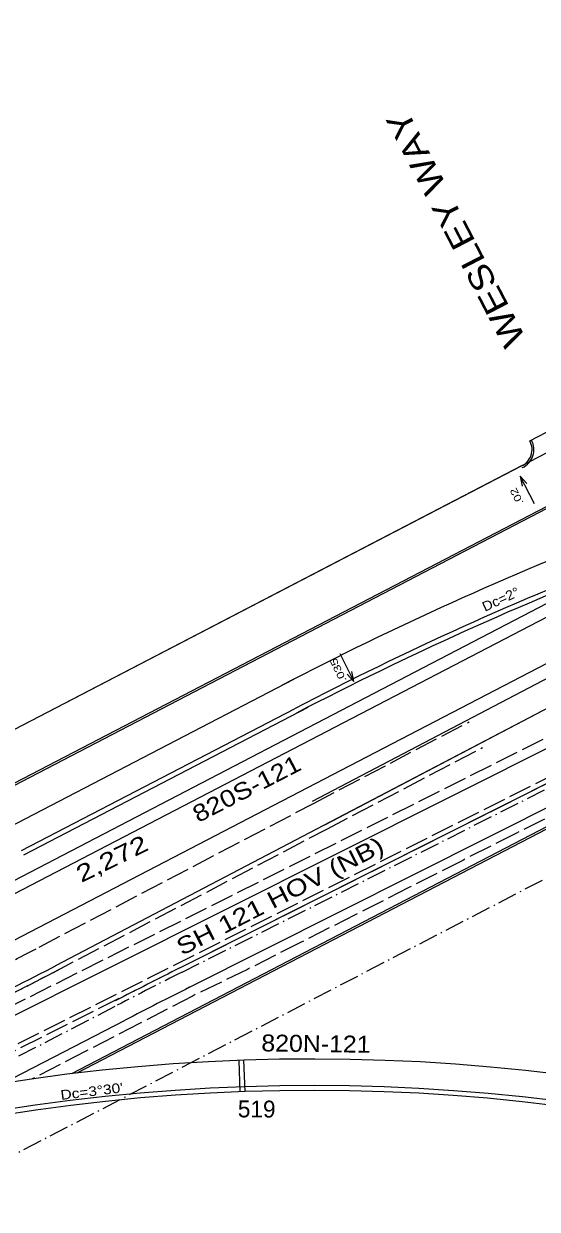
# Model space of a CAD drawing. Extents: x 2354993 to 2372084, y 6966390 to 6990057.
# Drawn here: x 2363006 to 2363431, y 6978118 to 6979100 of the extents above; entities that cross this region are included whole.
import ezdxf
from ezdxf.enums import TextEntityAlignment as Align

# ---------------------------------------------------------------- set-up
doc = ezdxf.new("R2010")
doc.units = 0
doc.header["$LTSCALE"] = 3.2
doc.linetypes.add('DOT_DASHED', pattern=[7.7, 5, -1.2, 0.3, -1.2])
doc.linetypes.add('LONG_DASHED', pattern=[7.5, 6, -1.5])
for name, color, linetype, lineweight in [('13', 7, 'Continuous', 13), ('17', 7, 'Continuous', 13), ('19', 7, 'Continuous', 13), ('25', 7, 'Continuous', 13), ('4', 7, 'Continuous', 13), ('5', 7, 'Continuous', 13), ('6', 7, 'Continuous', 13), ('9', 7, 'Continuous', 13)]:
    doc.layers.add(name, color=color, linetype=linetype, lineweight=lineweight)

msp = doc.modelspace()

# ---------------------------------------------------------------- linework, layer by layer
at = {"layer": '17'}
for p, q in [((2363268.695, 6978481.439), (2363677.359, 6978693.821)), ((2363183.998, 6978240.992), (2363184.891, 6978215.034)), ((2363187.996, 6978241.129), (2363188.889, 6978215.172))]:
    msp.add_line(p, q, dxfattribs=at)
at = {"layer": '19'}
for p, q in [((2363417.054, 6978724.995), (2363418.784, 6978716.872)), ((2363417.054, 6978724.995), (2363422.81, 6978719)), ((2363429.128, 6978702.214), (2363417.054, 6978724.995)), ((2363267.755, 6978578.025), (2363279.347, 6978554.995)), ((2363279.347, 6978554.995), (2363273.719, 6978561.11)), ((2363279.347, 6978554.995), (2363277.788, 6978563.153))]:
    msp.add_line(p, q, dxfattribs=at)
at = {"layer": '25'}
for p, q in [((2363038.234, 6978322.559), (2364007.4, 6978830.292)), ((2358006.591, 6975920.846), (2363488.891, 6978770.331)), ((2362811.106, 6978184.667), (2363604.71, 6978582.7)), ((2363003.914, 6978414.83), (2363230.047, 6978532.352)), ((2363143.211, 6978301.576), (2363589.111, 6978525.607)), ((2362988.207, 6978222.005), (2363089.737, 6978274.358))]:
    msp.add_line(p, q, dxfattribs=at)
at = {"layer": '25', "linetype": 'LONG_DASHED'}
for p, q in [((2362775.435, 6978175.726), (2363601.123, 6978589.851)), ((2363618.55, 6978565.019), (2362905.562, 6978206.794)), ((2363135.13, 6978317.66), (2363581.03, 6978541.691)), ((2363245.903, 6978453.932), (2363374.908, 6978521.516)), ((2363257.039, 6978432.672), (2363386.045, 6978500.257)), ((2363018.694, 6978334.9), (2363245.903, 6978453.932)), ((2363458.934, 6978451.609), (2363414.156, 6978429.36)), ((2363029.83, 6978313.64), (2363257.039, 6978432.672)), ((2363414.13, 6978429.346), (2363369.523, 6978406.758)), ((2363369.523, 6978406.757), (2363324.916, 6978384.169)), ((2363324.916, 6978384.168), (2363280.309, 6978361.58)), ((2363280.309, 6978361.579), (2363235.702, 6978338.991)), ((2363235.702, 6978338.99), (2363191.095, 6978316.402)), ((2363191.154, 6978316.43), (2363146.169, 6978294.605)), ((2363084.717, 6978292.33), (2362920.65, 6978209.898)), ((2363146.082, 6978294.561), (2363101.663, 6978271.606)), ((2363101.663, 6978271.606), (2363057.244, 6978248.651)), ((2363057.244, 6978248.651), (2363012.825, 6978225.696))]:
    msp.add_line(p, q, dxfattribs=at)
at = {"layer": '25'}
for centre, radius, start, end in [((2364544.669, 6976002.774), 2850.789, 111.22127, 117.46089), ((2365709.196, 6973194.37), 5715.578, 116.67607, 117.27757)]:
    msp.add_arc(centre, radius, start, end, dxfattribs=at)
at = {"layer": '25', "linetype": 'LONG_DASHED'}
for centre, radius, start, end in [((2361957.93, 6980359.697), 2285.831, 293.48147, 297.64944), ((2361957.927, 6980359.696), 2309.831, 293.48137, 297.6495), ((2365709.196, 6973194.37), 5733.578, 116.67607, 117.27757)]:
    msp.add_arc(centre, radius, start, end, dxfattribs=at)
at = {"layer": '4'}
msp.add_line((2362757.154, 6978215.587), (2363268.695, 6978481.438), dxfattribs=at)
at = {"layer": '5'}
for p, q in [((2363255.18, 6978436.214), (2364007.4, 6978830.292)), ((2363244.971, 6978455.701), (2363891.715, 6978794.521)), ((2363425.177, 6978754.243), (2363463.775, 6978774.478)), ((2362087.371, 6978041.876), (2363419.143, 6978734.078)), ((2362654.988, 6978292.473), (2363507.292, 6978735.395)), ((2362655.626, 6978291.114), (2363508.018, 6978734.082)), ((2362391.142, 6978063.692), (2363583.984, 6978683.611)), ((2363248.405, 6978520.48), (2363498.513, 6978650.46)), ((2362993.757, 6978434.346), (2363229.499, 6978556.861)), ((2363135.13, 6978317.66), (2363581.03, 6978541.691)), ((2363005.748, 6978411.277), (2363241.489, 6978533.791)), ((2363620.009, 6978528.496), (2363045.424, 6978230.005)), ((2362329.78, 6978043.07), (2363248.405, 6978520.479)), ((2363620.695, 6978527.162), (2363049.66, 6978230.516))]:
    msp.add_line(p, q, dxfattribs=at)
for centre, radius, start, end in [((2363412.177, 6978747.044), 14.86, 294.19474, 28.97554), ((2363412.177, 6978747.044), 16.36, 294.19474, 28.97554), ((2364544.669, 6976002.774), 2872.789, 111.22127, 117.46089), ((2364544.669, 6976002.774), 2846.789, 111.22127, 117.46089), ((2361968.189, 6980365.073), 2305.831, 293.48164, 297.64942), ((2361968.189, 6980365.073), 2309.831, 293.48164, 297.64942), ((2365709.196, 6973194.37), 5733.578, 116.67607, 117.27757), ((2363244.672, 6976597.082), 1645.014, 38.12295, 103.3303), ((2363244.672, 6976597.082), 1623.014, 38.12295, 103.3303), ((2363244.672, 6976597.082), 1619.014, 38.12295, 103.3303)]:
    msp.add_arc(centre, radius, start, end, dxfattribs=at)
at = {"layer": '6', "linetype": 'DOT_DASHED'}
for p, q in [((2363136.926, 6978314.086), (2363582.826, 6978538.117)), ((2360272.717, 6976747.357), (2363548.144, 6978448.903)), ((2360272.718, 6976747.358), (2363548.137, 6978448.9)), ((2360272.718, 6976747.358), (2363548.137, 6978448.9)), ((2362716.922, 6978097.869), (2363083.321, 6978286.801))]:
    msp.add_line(p, q, dxfattribs=at)
msp.add_arc((2365709.196, 6973194.37), 5729.578, 116.67607, 117.27757, dxfattribs=at)
at = {"layer": '9'}
msp.add_arc((2360722.521, 6984327.136), 5729.573, 359.50797, 359.50797, dxfattribs=at)

# ---------------------------------------------------------------- texts
at = {"layer": '13', "width": 1.2}
msp.add_text('WESLEY WAY', height=20, rotation=117.447, dxfattribs=at).set_placement((2363372.707, 6978934.43), align=Align.CENTER)
at = {"layer": '13'}
for s, rotation, width, p in [('820S-121', 27.223, 1.2, (2363150.343, 6978437.629)), ('2,272', 26.014, 1.35, (2363053.466, 6978387.998)), ('SH 121 HOV (NB)', 27.223, 1.25, (2363136.887, 6978327.523)), ('820N-121', 359.235, 1.1, (2363202.628, 6978248.531))]:
    msp.add_text(s, height=14, rotation=rotation, dxfattribs=dict(at, width=width)).set_placement(p)
msp.add_text('519', height=14, rotation=359.616, dxfattribs=at).set_placement((2363183.176, 6978193.859))
at = {"layer": '17'}
for s, height, rotation, width, p in [('Dc=2°', 7.999, 24.802, 1.1, (2363387.985, 6978612.641)), ("Dc=3°30'", 8, 7.036, 1.2, (2363036.778, 6978208.259))]:
    msp.add_text(s, height=height, rotation=rotation, dxfattribs=dict(at, width=width)).set_placement(p)
at = {"layer": '19'}
for s, height, rotation, width, p in [('.02', 6, 117.046, 1.3, (2363420.257, 6978703.128)), ('.035', 5.999, 115.33, 1.35, (2363273.564, 6978555.991))]:
    msp.add_text(s, height=height, rotation=rotation, dxfattribs=dict(at, width=width)).set_placement(p)

doc.saveas('drawing.dxf')
